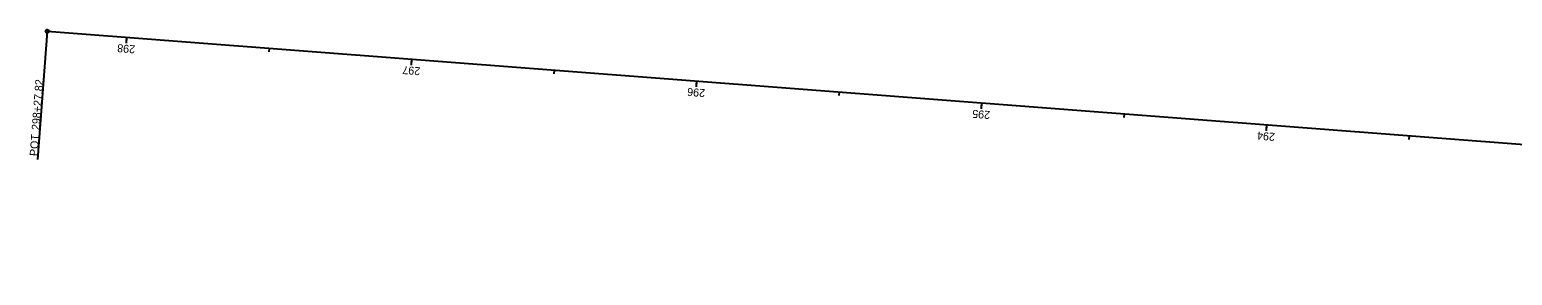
# Model space of a CAD drawing. Extents: x 2045805 to 2050091, y 455249 to 458900.
# Drawn here: x 2045805 to 2046324, y 457269 to 457355 of the extents above; entities that cross this region are included whole.
import ezdxf

# ---------------------------------------------------------------- set-up
doc = ezdxf.new("R2010")
doc.units = 0
for name, color, linetype in [('GE_P_Alignment_100_Bearings', 7, 'Continuous'), ('GE_P_Alignment_100_Cardinal_Points', 7, 'Continuous'), ('GE_P_Alignment_100_Distances', 7, 'Continuous'), ('GE_P_Alignment_100_Stations', 7, 'Continuous'), ('PF_P_Grade_Line', 7, 'Continuous'), ('PV_P_EOP', 7, 'Continuous'), ('PV_X_EOP', 7, 'Continuous')]:
    doc.layers.add(name, color=color, linetype=linetype)

msp = doc.modelspace()

# ---------------------------------------------------------------- linework, layer by layer
at = {"layer": 'GE_P_Alignment_100_Bearings'}
msp.add_line((2045811.12, 457354.01), (2045807.67, 457309.15), dxfattribs=at)
msp.add_circle((2045811.12, 457354.01), 0.6, dxfattribs=at)
at = {"layer": 'GE_P_Alignment_100_Cardinal_Points'}
for p, q in [((2045838.85, 457351.88), (2045838.7, 457349.89)), ((2045888.71, 457348.05), (2045888.62, 457346.86)), ((2045938.56, 457344.22), (2045938.41, 457342.23)), ((2045988.41, 457340.39), (2045988.32, 457339.2)), ((2046038.27, 457336.56), (2046038.11, 457334.57)), ((2046088.12, 457332.73), (2046088.03, 457331.54)), ((2046137.97, 457328.9), (2046137.82, 457326.91)), ((2046187.83, 457325.07), (2046187.73, 457323.87)), ((2046237.68, 457321.24), (2046237.53, 457319.25)), ((2046287.53, 457317.41), (2046287.44, 457316.21))]:
    msp.add_line(p, q, dxfattribs=at)
at = {"layer": 'GE_P_Alignment_100_Distances'}
msp.add_line((2045811.12, 457354.01), (2045807.67, 457309.15), dxfattribs=at)
msp.add_circle((2045811.12, 457354.01), 0.6, dxfattribs=at)
at = {"layer": 'GE_P_Alignment_100_Stations'}
for p, q in [((2045838.85, 457351.88), (2045838.76, 457350.69)), ((2045938.56, 457344.22), (2045938.47, 457343.03)), ((2046038.27, 457336.56), (2046038.17, 457335.37)), ((2046137.97, 457328.9), (2046137.82, 457326.91)), ((2046237.68, 457321.24), (2046237.59, 457320.04))]:
    msp.add_line(p, q, dxfattribs=at)
at = {"layer": 'PF_P_Grade_Line'}
msp.add_line((2045811.12, 457354.01), (2045807.67, 457309.15), dxfattribs=at)
msp.add_circle((2045811.12, 457354.01), 0.6, dxfattribs=at)
at = {"layer": 'PV_P_EOP'}
msp.add_line((2046922.17, 457268.65), (2045811.12, 457354.01), dxfattribs=at)
at = {"layer": 'PV_X_EOP'}
msp.add_line((2046137.97, 457328.9), (2046137.88, 457327.7), dxfattribs=at)

# ---------------------------------------------------------------- texts
at = {"layer": 'GE_P_Alignment_100_Bearings'}
for s, p in [('298+27.82', (2045808.41, 457319.38)), ('POT', (2045807.71, 457310.27))]:
    msp.add_text(s, height=2.8, rotation=85.6064, dxfattribs=at).set_placement(p)
at = {"layer": 'GE_P_Alignment_100_Cardinal_Points'}
for s, p in [('298', (2045841.93, 457349.09)), ('297', (2045941.69, 457341.43)), ('296', (2046041.35, 457333.77)), ('295', (2046141.06, 457326.11)), ('294', (2046240.71, 457318.45))]:
    msp.add_text(s, height=2.8, rotation=175.6064, dxfattribs=at).set_placement(p)
at = {"layer": 'GE_P_Alignment_100_Distances'}
for s, p in [('298+27.82', (2045808.41, 457319.38)), ('POT', (2045807.71, 457310.27))]:
    msp.add_text(s, height=2.8, rotation=85.6064, dxfattribs=at).set_placement(p)
at = {"layer": 'GE_P_Alignment_100_Stations'}
msp.add_text('295', height=2.8, rotation=175.6064, dxfattribs=at).set_placement((2046141.06, 457326.11))
at = {"layer": 'PF_P_Grade_Line'}
for s, p in [('298+27.82', (2045808.41, 457319.38)), ('POT', (2045807.71, 457310.27))]:
    msp.add_text(s, height=2.8, rotation=85.6064, dxfattribs=at).set_placement(p)

doc.saveas('drawing.dxf')
